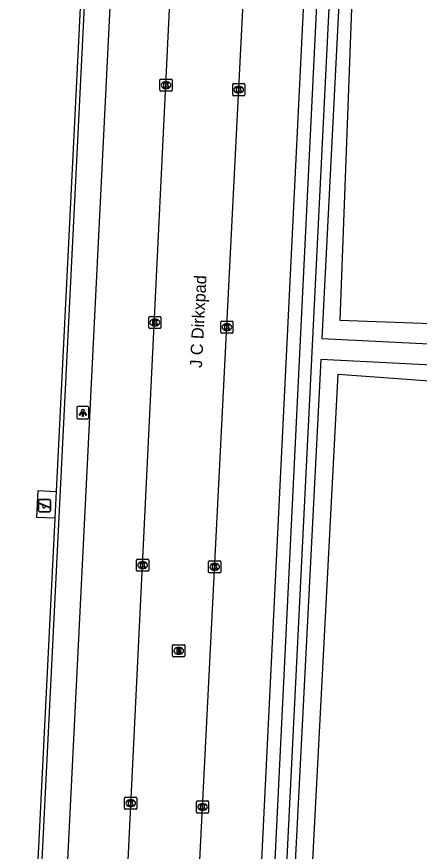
# Model space of a CAD drawing. Extents: x 161761 to 162722, y 384793 to 385405.
# Drawn here: x 162392.9 to 162426.2, y 385250.7 to 385319.7 of the extents above; entities that cross this region are included whole.
import ezdxf

# ---------------------------------------------------------------- set-up
doc = ezdxf.new("R2010")
doc.units = 0
for name, color, linetype in [('IMGEO_Grasland_overig', 7, 'Continuous'), ('IMGEO_Groenvoorziening', 7, 'Continuous'), ('IMGEO_Kolk', 7, 'Continuous'), ('IMGEO_Lichtpunt', 7, 'Continuous'), ('IMGEO_Loofbos', 7, 'Continuous'), ('IMGEO_Openbare_ruimte_label', 7, 'Continuous'), ('IMGEO_Parkeervlak_open', 7, 'Continuous'), ('IMGEO_Rijbaan_lokaal_open', 7, 'Continuous'), ('IMGEO_Rioolput', 7, 'Continuous'), ('IMGEO_Speelvoorziening', 7, 'Continuous'), ('IMGEO_Voetpad_open', 7, 'Continuous'), ('IMGEO_Waterloop', 7, 'Continuous')]:
    doc.layers.add(name, color=color, linetype=linetype)

msp = doc.modelspace()

# ---------------------------------------------------------------- linework, layer by layer
at = {"layer": 'IMGEO_Grasland_overig'}
msp.add_lwpolyline([(162421.908, 385355.651), (162419.635, 385294.602), (162436.99, 385293.977), (162478.245, 385291.84), (162477.196, 385287.088)], dxfattribs=at)
at = {"layer": 'IMGEO_Groenvoorziening'}
msp.add_lwpolyline([(162419.401, 385355.707), (162414.261, 385250), (162407.783, 385119.36)], dxfattribs=at)
at = {"layer": 'IMGEO_Kolk'}
for p, q in [((162404.772, 385313.596), (162404.772, 385314.448)), ((162404.847, 385314.522), (162405.699, 385314.522)), ((162405.26, 385314.302), (162405.285, 385314.302)), ((162405.773, 385314.448), (162405.773, 385313.596)), ((162405.699, 385313.522), (162404.847, 385313.522)), ((162405.283, 385313.742), (162405.258, 385313.742)), ((162410.775, 385313.223), (162410.775, 385314.075)), ((162410.85, 385314.149), (162411.702, 385314.149)), ((162411.263, 385313.929), (162411.288, 385313.929)), ((162411.776, 385314.075), (162411.776, 385313.223)), ((162411.702, 385313.149), (162410.85, 385313.149)), ((162411.286, 385313.369), (162411.261, 385313.369)), ((162403.922, 385294.913), (162404.774, 385294.913)), ((162403.847, 385293.987), (162403.847, 385294.839)), ((162404.335, 385294.693), (162404.36, 385294.693)), ((162404.848, 385294.839), (162404.848, 385293.987)), ((162409.799, 385293.603), (162409.799, 385294.455)), ((162409.874, 385294.529), (162410.726, 385294.529)), ((162410.287, 385294.309), (162410.312, 385294.309)), ((162410.8, 385294.455), (162410.8, 385293.603)), ((162404.774, 385293.913), (162403.922, 385293.913)), ((162404.358, 385294.133), (162404.333, 385294.133)), ((162410.726, 385293.529), (162409.874, 385293.529)), ((162410.31, 385293.749), (162410.285, 385293.749)), ((162402.914, 385274.863), (162403.766, 385274.863)), ((162402.839, 385273.937), (162402.839, 385274.789)), ((162403.327, 385274.643), (162403.352, 385274.643)), ((162403.84, 385274.789), (162403.84, 385273.937)), ((162408.79, 385273.798), (162408.79, 385274.65)), ((162408.865, 385274.724), (162409.717, 385274.724)), ((162409.278, 385274.504), (162409.303, 385274.504)), ((162409.791, 385274.65), (162409.791, 385273.798)), ((162403.766, 385273.863), (162402.914, 385273.863)), ((162403.35, 385274.083), (162403.325, 385274.083)), ((162409.717, 385273.724), (162408.865, 385273.724)), ((162409.301, 385273.944), (162409.276, 385273.944)), ((162401.853, 385254.27), (162401.853, 385255.122)), ((162401.928, 385255.196), (162402.78, 385255.196)), ((162402.341, 385254.976), (162402.366, 385254.976)), ((162402.854, 385255.122), (162402.854, 385254.27)), ((162407.864, 385254.89), (162408.716, 385254.89)), ((162402.78, 385254.196), (162401.928, 385254.196)), ((162402.364, 385254.416), (162402.339, 385254.416)), ((162407.789, 385253.964), (162407.789, 385254.816)), ((162408.277, 385254.67), (162408.302, 385254.67)), ((162408.79, 385254.816), (162408.79, 385253.964)), ((162408.716, 385253.89), (162407.864, 385253.89)), ((162408.3, 385254.11), (162408.275, 385254.11))]:
    msp.add_line(p, q, dxfattribs=at)
for points in [[(162404.772, 385313.596), (162404.772, 385314.448)], [(162404.847, 385314.522), (162405.699, 385314.522)], [(162405.093, 385314.222), (162405.216, 385314.222), (162405.216, 385314.071), (162405.346, 385314.222), (162405.51, 385314.222), (162405.364, 385314.071), (162405.517, 385313.822), (162405.365, 385313.822), (162405.28, 385313.986), (162405.216, 385313.919), (162405.216, 385313.822), (162405.093, 385313.822), (162405.093, 385314.222)], [(162405.773, 385314.448), (162405.773, 385313.596)], [(162405.699, 385313.522), (162404.847, 385313.522)], [(162410.775, 385313.223), (162410.775, 385314.075)], [(162410.85, 385314.149), (162411.702, 385314.149)], [(162411.096, 385313.849), (162411.219, 385313.849), (162411.219, 385313.698), (162411.349, 385313.849), (162411.513, 385313.849), (162411.367, 385313.698), (162411.52, 385313.449), (162411.368, 385313.449), (162411.283, 385313.613), (162411.219, 385313.546), (162411.219, 385313.449), (162411.096, 385313.449), (162411.096, 385313.849)], [(162411.776, 385314.075), (162411.776, 385313.223)], [(162411.702, 385313.149), (162410.85, 385313.149)], [(162403.922, 385294.913), (162404.774, 385294.913)], [(162403.847, 385293.987), (162403.847, 385294.839)], [(162404.168, 385294.613), (162404.291, 385294.613), (162404.291, 385294.462), (162404.421, 385294.613), (162404.585, 385294.613), (162404.439, 385294.462), (162404.592, 385294.213), (162404.44, 385294.213), (162404.355, 385294.377), (162404.291, 385294.31), (162404.291, 385294.213), (162404.168, 385294.213), (162404.168, 385294.613)], [(162404.848, 385294.839), (162404.848, 385293.987)], [(162409.799, 385293.603), (162409.799, 385294.455)], [(162409.874, 385294.529), (162410.726, 385294.529)], [(162410.12, 385294.229), (162410.243, 385294.229), (162410.243, 385294.078), (162410.373, 385294.229), (162410.537, 385294.229), (162410.391, 385294.078), (162410.544, 385293.829), (162410.392, 385293.829), (162410.307, 385293.993), (162410.243, 385293.926), (162410.243, 385293.829), (162410.12, 385293.829), (162410.12, 385294.229)], [(162410.8, 385294.455), (162410.8, 385293.603)], [(162404.774, 385293.913), (162403.922, 385293.913)], [(162410.726, 385293.529), (162409.874, 385293.529)], [(162402.914, 385274.863), (162403.766, 385274.863)], [(162402.839, 385273.937), (162402.839, 385274.789)], [(162403.16, 385274.563), (162403.283, 385274.563), (162403.283, 385274.412), (162403.413, 385274.563), (162403.577, 385274.563), (162403.431, 385274.412), (162403.584, 385274.163), (162403.432, 385274.163), (162403.347, 385274.327), (162403.283, 385274.26), (162403.283, 385274.163), (162403.16, 385274.163), (162403.16, 385274.563)], [(162403.84, 385274.789), (162403.84, 385273.937)], [(162408.79, 385273.798), (162408.79, 385274.65)], [(162408.865, 385274.724), (162409.717, 385274.724)], [(162409.111, 385274.424), (162409.234, 385274.424), (162409.234, 385274.273), (162409.364, 385274.424), (162409.528, 385274.424), (162409.382, 385274.273), (162409.535, 385274.024), (162409.383, 385274.024), (162409.298, 385274.188), (162409.234, 385274.121), (162409.234, 385274.024), (162409.111, 385274.024), (162409.111, 385274.424)], [(162409.791, 385274.65), (162409.791, 385273.798)], [(162403.766, 385273.863), (162402.914, 385273.863)], [(162409.717, 385273.724), (162408.865, 385273.724)], [(162401.853, 385254.27), (162401.853, 385255.122)], [(162401.928, 385255.196), (162402.78, 385255.196)], [(162402.174, 385254.896), (162402.297, 385254.896), (162402.297, 385254.745), (162402.427, 385254.896), (162402.591, 385254.896), (162402.445, 385254.745), (162402.598, 385254.496), (162402.446, 385254.496), (162402.361, 385254.66), (162402.297, 385254.593), (162402.297, 385254.496), (162402.174, 385254.496), (162402.174, 385254.896)], [(162402.854, 385255.122), (162402.854, 385254.27)], [(162407.864, 385254.89), (162408.716, 385254.89)], [(162402.78, 385254.196), (162401.928, 385254.196)], [(162407.789, 385253.964), (162407.789, 385254.816)], [(162408.11, 385254.59), (162408.233, 385254.59), (162408.233, 385254.439), (162408.363, 385254.59), (162408.527, 385254.59), (162408.381, 385254.439), (162408.534, 385254.19), (162408.382, 385254.19), (162408.297, 385254.354), (162408.233, 385254.287), (162408.233, 385254.19), (162408.11, 385254.19), (162408.11, 385254.59)], [(162408.79, 385254.816), (162408.79, 385253.964)], [(162408.716, 385253.89), (162407.864, 385253.89)]]:
    msp.add_lwpolyline(points, dxfattribs=at)
for centre, start, end in [((162404.849, 385314.446), 91.55205, 178.44795), ((162404.849, 385314.446), 91.55205, 178.44795), ((162405.697, 385314.446), 1.55205, 88.44795), ((162405.697, 385314.446), 1.55205, 88.44795), ((162404.849, 385313.598), 181.55205, 268.44795), ((162404.849, 385313.598), 181.55205, 268.44795), ((162405.697, 385313.598), 271.55205, 358.44795), ((162405.697, 385313.598), 271.55205, 358.44795), ((162410.852, 385314.073), 91.55205, 178.44795), ((162410.852, 385314.073), 91.55205, 178.44795), ((162411.7, 385314.073), 1.55205, 88.44795), ((162411.7, 385314.073), 1.55205, 88.44795), ((162410.852, 385313.225), 181.55205, 268.44795), ((162410.852, 385313.225), 181.55205, 268.44795), ((162411.7, 385313.225), 271.55205, 358.44795), ((162411.7, 385313.225), 271.55205, 358.44795), ((162403.924, 385294.837), 91.55205, 178.44795), ((162403.924, 385294.837), 91.55205, 178.44795), ((162404.772, 385294.837), 1.55205, 88.44795), ((162404.772, 385294.837), 1.55205, 88.44795), ((162409.876, 385294.453), 91.55205, 178.44795), ((162409.876, 385294.453), 91.55205, 178.44795), ((162410.724, 385294.453), 1.55205, 88.44795), ((162410.724, 385294.453), 1.55205, 88.44795), ((162403.924, 385293.989), 181.55205, 268.44795), ((162403.924, 385293.989), 181.55205, 268.44795), ((162404.772, 385293.989), 271.55205, 358.44795), ((162404.772, 385293.989), 271.55205, 358.44795), ((162409.876, 385293.605), 181.55205, 268.44795), ((162409.876, 385293.605), 181.55205, 268.44795), ((162410.724, 385293.605), 271.55205, 358.44795), ((162410.724, 385293.605), 271.55205, 358.44795), ((162402.916, 385274.787), 91.55205, 178.44795), ((162402.916, 385274.787), 91.55205, 178.44795), ((162403.764, 385274.787), 1.55205, 88.44795), ((162403.764, 385274.787), 1.55205, 88.44795), ((162408.867, 385274.648), 91.55205, 178.44795), ((162408.867, 385274.648), 91.55205, 178.44795), ((162409.715, 385274.648), 1.55205, 88.44795), ((162409.715, 385274.648), 1.55205, 88.44795), ((162402.916, 385273.939), 181.55205, 268.44795), ((162402.916, 385273.939), 181.55205, 268.44795), ((162403.764, 385273.939), 271.55205, 358.44795), ((162403.764, 385273.939), 271.55205, 358.44795), ((162408.867, 385273.8), 181.55205, 268.44795), ((162408.867, 385273.8), 181.55205, 268.44795), ((162409.715, 385273.8), 271.55205, 358.44795), ((162409.715, 385273.8), 271.55205, 358.44795), ((162401.93, 385255.12), 91.55205, 178.44795), ((162401.93, 385255.12), 91.55205, 178.44795), ((162402.778, 385255.12), 1.55205, 88.44795), ((162402.778, 385255.12), 1.55205, 88.44795), ((162407.866, 385254.814), 91.55205, 178.44795), ((162407.866, 385254.814), 91.55205, 178.44795), ((162408.714, 385254.814), 1.55205, 88.44795), ((162408.714, 385254.814), 1.55205, 88.44795), ((162401.93, 385254.272), 181.55205, 268.44795), ((162401.93, 385254.272), 181.55205, 268.44795), ((162402.778, 385254.272), 271.55205, 358.44795), ((162402.778, 385254.272), 271.55205, 358.44795), ((162407.866, 385253.966), 181.55205, 268.44795), ((162407.866, 385253.966), 181.55205, 268.44795), ((162408.714, 385253.966), 271.55205, 358.44795), ((162408.714, 385253.966), 271.55205, 358.44795)]:
    msp.add_arc(centre, 0.0765, start, end, dxfattribs=at)
for centre, major_axis, ratio, start_param, end_param in [((162405.259, 385314.022), (-0.387, 0.002), 0.722429, 4.712389, 7.853982), ((162405.284, 385314.022), (-0.39, 0.002), 0.717154, 1.570796, 4.712389), ((162411.262, 385313.649), (-0.387, 0.002), 0.722429, 4.712389, 7.853982), ((162411.287, 385313.649), (-0.39, 0.002), 0.717154, 1.570796, 4.712389), ((162404.334, 385294.413), (-0.387, 0.002), 0.722429, 4.712389, 7.853982), ((162404.359, 385294.413), (-0.39, 0.002), 0.717154, 1.570796, 4.712389), ((162410.286, 385294.029), (-0.387, 0.002), 0.722429, 4.712389, 7.853982), ((162410.311, 385294.029), (-0.39, 0.002), 0.717154, 1.570796, 4.712389), ((162403.326, 385274.363), (-0.387, 0.002), 0.722429, 4.712389, 7.853982), ((162403.351, 385274.363), (-0.39, 0.002), 0.717154, 1.570796, 4.712389), ((162409.277, 385274.224), (-0.387, 0.002), 0.722429, 4.712389, 7.853982), ((162409.302, 385274.224), (-0.39, 0.002), 0.717154, 1.570796, 4.712389), ((162402.34, 385254.696), (-0.387, 0.002), 0.722429, 4.712389, 7.853982), ((162402.365, 385254.696), (-0.39, 0.002), 0.717154, 1.570796, 4.712389), ((162408.276, 385254.39), (-0.387, 0.002), 0.722429, 4.712389, 7.853982), ((162408.301, 385254.39), (-0.39, 0.002), 0.717154, 1.570796, 4.712389)]:
    msp.add_ellipse(centre, major_axis=major_axis, ratio=ratio, start_param=start_param, end_param=end_param, dxfattribs=at)
at = {"layer": 'IMGEO_Lichtpunt'}
for p, q in [((162397.903, 385287.366), (162397.903, 385286.559)), ((162397.903, 385287.366), (162397.903, 385286.559)), ((162398.805, 385287.461), (162397.997, 385287.461)), ((162398.805, 385287.461), (162397.997, 385287.461)), ((162398.899, 385286.559), (162398.899, 385287.366)), ((162398.899, 385286.559), (162398.899, 385287.366)), ((162397.997, 385286.465), (162398.805, 385286.465)), ((162397.997, 385286.465), (162398.805, 385286.465))]:
    msp.add_line(p, q, dxfattribs=at)
for points in [[(162398.277, 385287.03), (162398.316, 385287.002), (162398.128, 385286.74), (162398.09, 385286.767), (162398.277, 385287.03)], [(162398.379, 385286.982), (162398.426, 385286.982), (162398.426, 385286.66), (162398.379, 385286.66), (162398.379, 385286.982)], [(162398.489, 385287.002), (162398.527, 385287.029), (162398.714, 385286.767), (162398.675, 385286.739), (162398.489, 385287.002)]]:
    msp.add_lwpolyline(points, dxfattribs=at)
msp.add_circle((162398.402, 385287.164), 0.0994, dxfattribs=at)
for centre, start, end in [((162397.997, 385287.366), 90, 180), ((162397.997, 385287.366), 90, 180), ((162398.805, 385287.366), 0, 90), ((162398.805, 385287.366), 0, 90), ((162397.997, 385286.559), 180, 270), ((162397.997, 385286.559), 180, 270), ((162398.805, 385286.559), 270, 0), ((162398.805, 385286.559), 270, 360)]:
    msp.add_arc(centre, 0.0946, start, end, dxfattribs=at)
at = {"layer": 'IMGEO_Loofbos'}
msp.add_lwpolyline([(162408.166, 385119.329), (162410.582, 385119.132), (162417.396, 385250), (162419.486, 385290.14), (162434.994, 385289.014), (162477.196, 385287.088)], dxfattribs=at)
at = {"layer": 'IMGEO_Parkeervlak_open'}
msp.add_lwpolyline([(162407.031, 385124.711), (162413.183, 385250), (162418.351, 385355.761)], dxfattribs=at)
at = {"layer": 'IMGEO_Rijbaan_lokaal_open'}
for points in [[(162407.37, 385358.303), (162402.12, 385250), (162400.619, 385220.036)], [(162401.858, 385124.206), (162405.723, 385201.838), (162408.073, 385250), (162413.519, 385357.905)]]:
    msp.add_lwpolyline(points, dxfattribs=at)
at = {"layer": 'IMGEO_Rioolput'}
for p, q in [((162405.816, 385266.866), (162405.816, 385267.718)), ((162405.891, 385267.792), (162406.743, 385267.792)), ((162406.304, 385267.572), (162406.329, 385267.572)), ((162406.817, 385267.718), (162406.817, 385266.866)), ((162406.743, 385266.792), (162405.891, 385266.792)), ((162406.327, 385267.012), (162406.302, 385267.012))]:
    msp.add_line(p, q, dxfattribs=at)
for points in [[(162405.816, 385266.866), (162405.816, 385267.718)], [(162405.891, 385267.792), (162406.743, 385267.792)], [(162406.405, 385267.49), (162406.153, 385267.492), (162406.153, 385267.092)], [(162406.331, 385267.411), (162406.277, 385267.411), (162406.277, 385267.33)], [(162406.277, 385267.33), (162406.329, 385267.33)], [(162406.817, 385267.718), (162406.817, 385266.866)], [(162406.743, 385266.792), (162405.891, 385266.792)], [(162406.153, 385267.092), (162406.277, 385267.092), (162406.277, 385267.254), (162406.288, 385267.254)], [(162406.335, 385267.225), (162406.406, 385267.092), (162406.546, 385267.092), (162406.481, 385267.218)]]:
    msp.add_lwpolyline(points, dxfattribs=at)
for centre, radius, start, end in [((162405.893, 385267.716), 0.0765, 91.55205, 178.44795), ((162405.893, 385267.716), 0.0765, 91.55205, 178.44795), ((162406.313, 385267.519), 0.19, 274.7715, 282.96867), ((162406.337, 385267.315), 0.0964, 77.00612, 93.18647), ((162406.351, 385267.372), 0.0378, 276.66336, 79.67722), ((162406.404, 385267.38), 0.109, 350.36119, 89.41601), ((162406.402, 385267.38), 0.112, 277.58423, 350.98172), ((162406.386, 385267.165), 0.108, 29.51342, 73.79051), ((162406.741, 385267.716), 0.0765, 1.55205, 88.44795), ((162406.741, 385267.716), 0.0765, 1.55205, 88.44795), ((162405.893, 385266.868), 0.0765, 181.55205, 268.44795), ((162405.893, 385266.868), 0.0765, 181.55205, 268.44795), ((162406.287, 385267.201), 0.0533, 26.02933, 88.69889), ((162406.741, 385266.868), 0.0765, 271.55205, 358.44795), ((162406.741, 385266.868), 0.0765, 271.55205, 358.44795)]:
    msp.add_arc(centre, radius, start, end, dxfattribs=at)
for centre, major_axis, ratio, start_param, end_param in [((162406.303, 385267.292), (-0.387, 0.002), 0.722429, 4.712389, 7.853982), ((162406.328, 385267.292), (-0.39, 0.002), 0.717154, 1.570796, 4.712389)]:
    msp.add_ellipse(centre, major_axis=major_axis, ratio=ratio, start_param=start_param, end_param=end_param, dxfattribs=at)
at = {"layer": 'IMGEO_Speelvoorziening'}
for p, q in [((162394.73, 385278.885), (162394.73, 385279.685)), ((162394.73, 385279.685), (162394.73, 385278.885)), ((162394.83, 385279.785), (162395.62, 385279.785)), ((162395.62, 385279.785), (162394.83, 385279.785)), ((162395.72, 385279.685), (162395.72, 385278.885)), ((162395.72, 385278.885), (162395.72, 385279.685)), ((162395.113, 385279.313), (162394.774, 385279.45)), ((162394.799, 385279.51), (162395.675, 385279.157)), ((162395.651, 385279.097), (162395.311, 385279.234)), ((162395.62, 385278.785), (162394.83, 385278.785)), ((162394.83, 385278.785), (162395.62, 385278.785))]:
    msp.add_line(p, q, dxfattribs=at)
for centre, radius, start, end in [((162394.83, 385279.685), 0.1, 90, 180), ((162394.83, 385279.685), 0.1, 90, 180), ((162395.62, 385279.685), 0.1, 0, 90), ((162395.62, 385279.685), 0.1, 360, 90), ((162394.787, 385279.48), 0.0327, 68.07798, 248.07798), ((162395.192, 385279.223), 0.12, 130.99278, 5.16318), ((162395.663, 385279.127), 0.0327, 248.07798, 68.07798), ((162394.83, 385278.885), 0.1, 180, 270), ((162394.83, 385278.885), 0.1, 180, 270), ((162395.62, 385278.885), 0.1, 270, 0), ((162395.62, 385278.885), 0.1, 270, 0)]:
    msp.add_arc(centre, radius, start, end, dxfattribs=at)
at = {"layer": 'IMGEO_Voetpad_open'}
for points in [[(162402.407, 385356.546), (162397.139, 385250), (162395.761, 385222.299), (162398.543, 385222.074)], [(162393.284, 385214.705), (162395.038, 385250), (162400.23, 385354.495)], [(162399.185, 385340.905), (162399.108, 385339.342), (162396.191, 385280.46)], [(162396.081, 385278.236), (162394.607, 385278.308), (162394.712, 385280.534), (162396.191, 385280.46)], [(162396.191, 385280.46), (162396.081, 385278.236)], [(162396.081, 385278.236), (162394.682, 385250), (162392.939, 385214.821)]]:
    msp.add_lwpolyline(points, dxfattribs=at)
at = {"layer": 'IMGEO_Waterloop'}
msp.add_lwpolyline([(162418.132, 385293.078), (162476.312, 385290.198), (162475.895, 385288.42), (162418.045, 385291.37), (162409.407, 385121.965), (162408.945, 385121.989), (162420.33, 385352.734), (162421.172, 385352.691), (162418.132, 385293.078)], dxfattribs=at)

# ---------------------------------------------------------------- texts
at = {"layer": 'IMGEO_Openbare_ruimte_label'}
msp.add_text('J C Dirkxpad', height=1, rotation=87.13473, dxfattribs=at).set_placement((162408.237, 385290.651))

doc.saveas('drawing.dxf')
